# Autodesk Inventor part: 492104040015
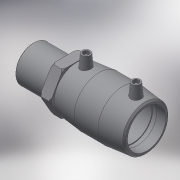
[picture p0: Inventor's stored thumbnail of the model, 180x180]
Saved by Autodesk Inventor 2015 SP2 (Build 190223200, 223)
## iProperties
Created: 2017-06
Part Number: 492104040015
Material: Generic
Description: PLASSON Male Transition Coupler 40 x 1.1/2"
Document SubType Name: Modeling
Designer: KIM
Mass: 162.815 g
Surface Area: 455.937 cm^2
Volume: 162.815 cm^3
Density: 1 g/cm^3
Appearance: Default
Author: KIM
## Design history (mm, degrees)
derived "492104.ipt"
feature "Solid1::492104.ipt"
tag "TaggingFeature1"
body "Solid1"
other parameters: "d0" = 97, "d2" = 56, "d3" = 47, "d4" = 32.33333, "d5" = 50.4, "d6" = 38, "d8" = 168 deg, "d10" = 18.8, "d11" = 6.26667, "d29" = 46, "d30" = 14, "d31" = 33.95, "d34" = 5 deg, "d41" = 4, "d42" = 14, "d43" = 0, "d48" = 3, "d49" = 0, "d57" = 29, "d58" = 47.803, "d59" = 38.2424, "d60" = 32.4, "d61" = 56, "d62" = 0.95606, "d65" = 1.68, "d70" = 0.1, "d71" = 36, "d72" = 9, "d73" = 18.8, "d75" = 0, "L_" = 133, "L_1" = 47, "D_1" = 56, "A_" = 46, "d_2" = 12, "L_2" = 36, "D_" = 29, "R_" = 47.803
